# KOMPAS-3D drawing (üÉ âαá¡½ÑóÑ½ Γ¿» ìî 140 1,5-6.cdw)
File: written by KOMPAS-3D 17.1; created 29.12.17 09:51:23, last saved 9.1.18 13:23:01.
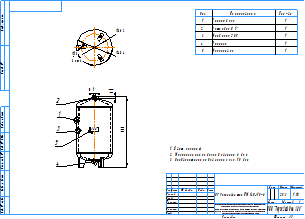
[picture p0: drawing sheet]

Sheet 1: A3, landscape

Title block, sheet 1: name: БР Гранлевел тип НМ 140/1,5-6; mass: 25,3; sheets: 1; sheet format: A3; stored path: \\Fsk1\files\АП\20_PKO\02_Насосное направление\Разработка\04_Проекты разные\Баки\КД действующая\Баки Flexcon R\Компас\Чертежи\БР Гранлевел тип НМ 140 1,5-6.cdw

Views: Проекционный вид 3, Проекционный вид 4
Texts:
  IvAn
  ADL
  Поз.
  Кол-во
  Корпус бака
  Мембрана SBR
  Патрубок G 1"
  Ниппель
  Маркировка
  АДЛ
  Цвет: красный
  Максимальное рабочее давление: 6 бар
  Предварительное давление газа: 1,5 бар
  ACAD_ISO03W100_RGB_223_127_255_SC_0.063_THICK_0.05
  ACAD_ISO03W100_RGB_223_127_255_SC_1_THICK_0.05
  Рама для чертежей
  Лит-Масса-Масштаб
  Материал-Предприятие
  Масштаб
  Изм.
  Лист
  № докум.
  Подп.
  Дата
  Лит.
  Разраб.
  Пров.
  Т.контр.
  Листов
  Внимание! Данный продукт является объектом авторского права ООО «Торговый Дом АДЛ».
  Запрещается изменение, копирование, распространение
  (в том числе путем копирования на другие сайты и ресурсы в Интернете)
  или любое иное использование информации и объектов без предварительного
  согласия правообладателя (ООО «Торговый Дом АДЛ»).
  Н.контр.
  Утв.
  ООО "Торговый дом АДЛ"
  Изменение
  Номер документа
  Подпись
  Обозначение документа
  Наименование изделия
  Масса изделия по ГОСТ 2.109-73
  Порядковый номер листа
  Общее количество листов в документе
  Характер работы, выполненной лицом, подписавшим документ
  Наименование или индекс предприятия, выпускающего документ
  Инв. № подл.
  Подп. и дата
  Взам. инв. №
  Инв. № дубл.
  Инвентарный номер подлинника по ГОСТ 2.501-68
  Подпись принявшего подлинник в отдел технической документации
  Инвентарный номер подлинника, взамен которого выпущен данный подлинник
  Инвентарный номер дубликата по ГОСТ 2.502-68
  Подпись принявшего дубликат в отдел технической документации
  Справ. №
  Перв. примен.
  Обозначение документа, взамен или на основании которого выпущен данный документ
  Обозначение документа, в котором впервые записан данный документ
  Подпись лица, копировавшего чертеж
  Обозначение формата листа
  !Рама для чертежа
Dimensions and other numbers on the sheet: 1; 3; 2; 4; 5; 950; 21; 362; 484; 13; 3 отв.; 1:10; 25,3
